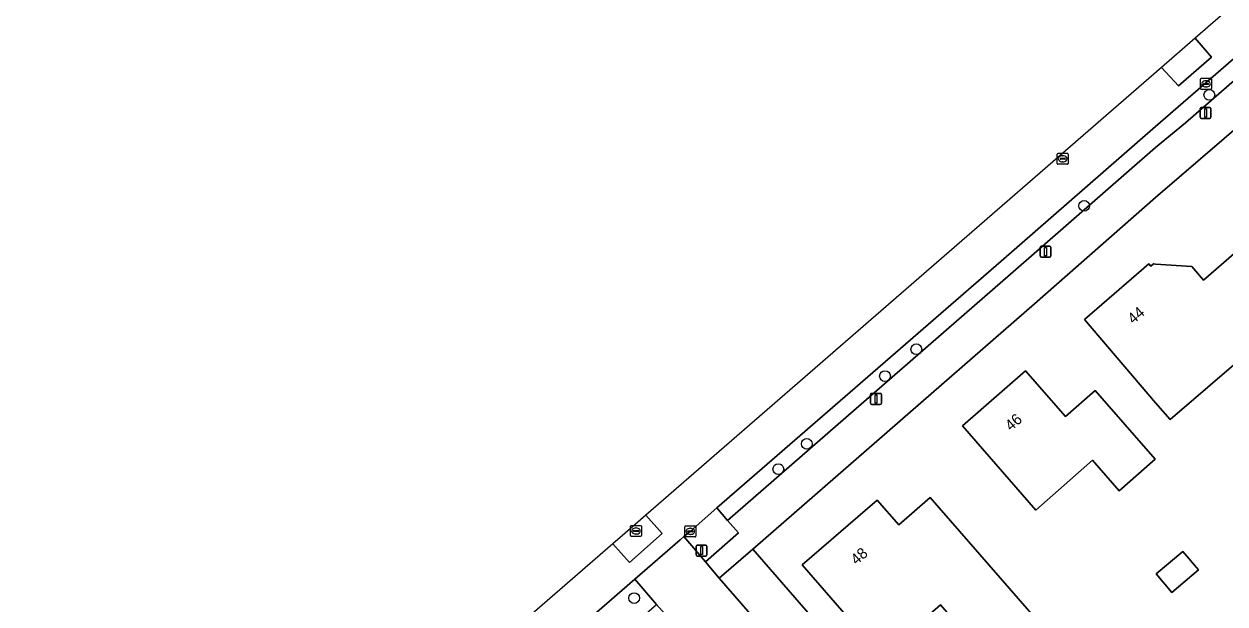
# Model space of a CAD drawing. Extents: x 155887 to 156869, y 383880 to 384678.
# Drawn here: x 155897.1 to 156006.3, y 384066 to 384118.8 of the extents above; entities that cross this region are included whole.
import ezdxf

# ---------------------------------------------------------------- set-up
doc = ezdxf.new("R2010")
doc.units = 0
for name, color, linetype in [('IMGEO_Boom', 7, 'Continuous'), ('IMGEO_Erf', 7, 'Continuous'), ('IMGEO_Groenvoorziening', 7, 'Continuous'), ('IMGEO_Kolk', 7, 'Continuous'), ('IMGEO_Lichtmast', 7, 'Continuous'), ('IMGEO_Pand', 7, 'Continuous'), ('IMGEO_Pand_nummerreeks', 7, 'Continuous'), ('IMGEO_Parkeervlak_open', 7, 'Continuous'), ('IMGEO_Rijbaan_lokaal_gesloten', 7, 'Continuous'), ('IMGEO_Rijbaan_lokaal_open', 7, 'Continuous'), ('IMGEO_Rioolput', 7, 'Continuous'), ('IMGEO_Verkeerseiland_groen', 7, 'Continuous'), ('IMGEO_Voetpad_open', 7, 'Continuous')]:
    doc.layers.add(name, color=color, linetype=linetype)

msp = doc.modelspace()

# ---------------------------------------------------------------- linework, layer by layer
at = {"layer": 'IMGEO_Boom'}
for centre in [(156004.89, 384112.32), (155993.51, 384102.23), (155978.24, 384089.19), (155975.39, 384086.75), (155968.28, 384080.59), (155965.69, 384078.29), (155952.58, 384066.56)]:
    msp.add_circle(centre, 0.489, dxfattribs=at)
at = {"layer": 'IMGEO_Erf'}
msp.add_lwpolyline([(156014.63, 384115.56), (156000, 384102.99), (155988.99, 384093.32), (155963.36, 384071.02), (155979.83, 384052.07), (155979.86, 384052.09), (155982.63, 384048.87), (155983.24, 384048.16), (155986.68, 384044.16), (155986.94, 384044.39), (155990.61, 384047.62), (155989.41, 384048.97), (155993.24, 384052.33), (155997.05, 384055.54), (155998.16, 384054.27), (156000, 384055.89), (156001.81, 384057.42), (156005.54, 384060.57), (156004.36, 384061.93), (156008.14, 384065.22)], dxfattribs=at)
for points in [[(156009.74, 384086.87), (156008.18, 384088.68), (156001.34, 384082.8), (156000, 384084.31), (155993.53, 384091.9), (155999.39, 384096.97), (155999.57, 384096.76), (155999.8, 384096.95), (156000, 384096.94), (156003.29, 384096.71), (156004.36, 384095.46), (156007.36, 384098.07), (156013.9, 384090.47)], [(155999.96, 384079.18), (155996.69, 384076.32), (155994.26, 384079.09), (155989.1, 384074.57), (155982.43, 384082.21), (155988.18, 384087.23), (155991.81, 384083.08), (155994.51, 384085.43)], [(155985.06, 384060.65), (155980.45, 384065.94), (155975.09, 384061.27), (155967.87, 384069.58), (155974.68, 384075.48), (155976.64, 384073.22), (155979.51, 384075.71), (155989.36, 384064.39)], [(156003.9, 384069.12), (156001.48, 384067.08), (156000.05, 384068.77), (156002.47, 384070.81)]]:
    msp.add_lwpolyline(points, close=True, dxfattribs=at)
at = {"layer": 'IMGEO_Groenvoorziening'}
msp.add_lwpolyline([(155979.86, 384052.09), (155979.83, 384052.07), (155963.36, 384071.02), (155960.32, 384068.38), (155979.58, 384046.21), (155982.63, 384048.87)], close=True, dxfattribs=at)
at = {"layer": 'IMGEO_Kolk'}
for p, q in [((156004.09, 384112.9), (156004.09, 384113.75)), ((156004.16, 384113.83), (156005.02, 384113.83)), ((156005.02, 384112.82), (156004.16, 384112.82)), ((156004.35, 384113.32), (156004.35, 384113.33)), ((156004.39, 384113.37), (156004.79, 384113.37)), ((156004.78, 384113.28), (156004.39, 384113.28)), ((156004.6, 384113.05), (156004.57, 384113.05)), ((156004.58, 384113.6), (156004.6, 384113.6)), ((156004.83, 384113.33), (156004.83, 384113.32)), ((156005.09, 384113.75), (156005.09, 384112.9)), ((155957.18, 384072.2), (155957.18, 384073.05)), ((155957.26, 384073.13), (155958.11, 384073.13)), ((155957.44, 384072.62), (155957.44, 384072.64)), ((155957.48, 384072.67), (155957.88, 384072.67)), ((155957.88, 384072.59), (155957.48, 384072.59)), ((155957.67, 384072.91), (155957.69, 384072.91)), ((155957.92, 384072.64), (155957.92, 384072.62)), ((155958.18, 384073.05), (155958.18, 384072.2)), ((155958.11, 384072.13), (155957.26, 384072.13)), ((155957.69, 384072.35), (155957.67, 384072.35))]:
    msp.add_line(p, q, dxfattribs=at)
for points in [[(156004.09, 384112.9), (156004.09, 384113.75)], [(156004.16, 384113.83), (156005.02, 384113.83)], [(156005.02, 384112.82), (156004.16, 384112.82)], [(156005.09, 384113.75), (156005.09, 384112.9)], [(155957.18, 384072.2), (155957.18, 384073.05)], [(155957.26, 384073.13), (155958.11, 384073.13)], [(155958.18, 384073.05), (155958.18, 384072.2)], [(155958.11, 384072.13), (155957.26, 384072.13)]]:
    msp.add_lwpolyline(points, dxfattribs=at)
for centre, radius, start, end in [((156004.16, 384113.75), 0.0765, 91.552, 178.448), ((156004.16, 384113.75), 0.0765, 91.552, 178.448), ((156004.16, 384112.9), 0.0765, 181.552, 268.448), ((156004.16, 384112.9), 0.0765, 181.552, 268.448), ((156004.39, 384113.33), 0.0403, 85.8775, 175.7526), ((156004.38, 384113.32), 0.0366, 178.938, 274.7102), ((156004.79, 384113.32), 0.043, 264.8664, 352.4533), ((156004.79, 384113.33), 0.0386, 1.7309, 96.639), ((156005.01, 384113.75), 0.0765, 1.552, 88.448), ((156005.01, 384113.75), 0.0765, 1.552, 88.448), ((156005.01, 384112.9), 0.0765, 271.552, 358.448), ((156005.01, 384112.9), 0.0765, 271.552, 358.448), ((155957.26, 384073.05), 0.0765, 91.552, 178.448), ((155957.26, 384073.05), 0.0765, 91.552, 178.448), ((155957.48, 384072.63), 0.0403, 85.8775, 175.7526), ((155957.48, 384072.62), 0.0366, 178.938, 274.7102), ((155957.89, 384072.63), 0.0386, 1.7309, 96.639), ((155957.88, 384072.63), 0.043, 264.8664, 352.4533), ((155958.11, 384073.05), 0.0765, 1.552, 88.448), ((155958.11, 384073.05), 0.0765, 1.552, 88.448), ((155957.26, 384072.2), 0.0765, 181.552, 268.448), ((155957.26, 384072.2), 0.0765, 181.552, 268.448), ((155958.11, 384072.2), 0.0765, 271.552, 358.448), ((155958.11, 384072.2), 0.0765, 271.552, 358.448)]:
    msp.add_arc(centre, radius, start, end, dxfattribs=at)
for centre, major_axis, ratio, start_param, end_param in [((156004.58, 384113.32), (-0.387, 0.002), 0.722429, 4.712389, 7.853982), ((156004.6, 384113.32), (-0.39, 0.002), 0.717154, 1.570796, 4.712389), ((155957.67, 384072.63), (-0.387, 0.002), 0.722429, 4.712389, 7.853982), ((155957.69, 384072.63), (-0.39, 0.002), 0.717154, 1.570796, 4.712389)]:
    msp.add_ellipse(centre, major_axis=major_axis, ratio=ratio, start_param=start_param, end_param=end_param, dxfattribs=at)
at = {"layer": 'IMGEO_Lichtmast'}
for p, q in [((156004.05, 384110.28), (156004.05, 384111.08)), ((156004.05, 384111.08), (156004.05, 384110.28)), ((156004.15, 384111.18), (156004.94, 384111.18)), ((156004.94, 384111.18), (156004.15, 384111.18)), ((156005.04, 384111.08), (156005.04, 384110.28)), ((156005.04, 384110.28), (156005.04, 384111.08)), ((156004.94, 384110.18), (156004.15, 384110.18)), ((156004.15, 384110.18), (156004.94, 384110.18)), ((155989.5, 384097.66), (155989.5, 384098.46)), ((155989.5, 384098.46), (155989.5, 384097.66)), ((155989.6, 384098.56), (155990.38, 384098.56)), ((155990.38, 384098.56), (155989.6, 384098.56)), ((155990.38, 384097.56), (155989.6, 384097.56)), ((155989.6, 384097.56), (155990.38, 384097.56)), ((155990.48, 384098.46), (155990.48, 384097.66)), ((155990.48, 384097.66), (155990.48, 384098.46)), ((155974.07, 384084.28), (155974.07, 384085.08)), ((155974.07, 384085.08), (155974.07, 384084.28)), ((155974.17, 384085.18), (155974.96, 384085.18)), ((155974.96, 384085.18), (155974.17, 384085.18)), ((155975.06, 384085.08), (155975.06, 384084.28)), ((155975.06, 384084.28), (155975.06, 384085.08)), ((155974.96, 384084.18), (155974.17, 384084.18)), ((155974.17, 384084.18), (155974.96, 384084.18)), ((155958.31, 384071.38), (155959.1, 384071.38)), ((155959.1, 384071.38), (155958.31, 384071.38)), ((155958.21, 384070.48), (155958.21, 384071.28)), ((155958.21, 384071.28), (155958.21, 384070.48)), ((155959.1, 384070.38), (155958.31, 384070.38)), ((155958.31, 384070.38), (155959.1, 384070.38)), ((155959.2, 384071.28), (155959.2, 384070.48)), ((155959.2, 384070.48), (155959.2, 384071.28))]:
    msp.add_line(p, q, dxfattribs=at)
for points in [[(156004.47, 384111.06), (156004.62, 384111.06), (156004.62, 384110.31), (156004.47, 384110.31), (156004.47, 384111.06)], [(155989.91, 384098.43), (155990.07, 384098.43), (155990.07, 384097.68), (155989.91, 384097.68), (155989.91, 384098.43)], [(155974.49, 384085.05), (155974.64, 384085.05), (155974.64, 384084.3), (155974.49, 384084.3), (155974.49, 384085.05)], [(155958.63, 384071.26), (155958.78, 384071.26), (155958.78, 384070.51), (155958.63, 384070.51), (155958.63, 384071.26)]]:
    msp.add_lwpolyline(points, dxfattribs=at)
for centre, start, end in [((156004.15, 384111.08), 90, 180), ((156004.15, 384111.08), 90, 180), ((156004.94, 384111.08), 0, 90), ((156004.94, 384111.08), 360, 90), ((156004.15, 384110.28), 180, 270), ((156004.15, 384110.28), 180, 270), ((156004.94, 384110.28), 270, 0), ((156004.94, 384110.28), 270, 0), ((155989.6, 384098.46), 90, 180), ((155989.6, 384098.46), 90, 180), ((155989.6, 384097.66), 180, 270), ((155989.6, 384097.66), 180, 270), ((155990.38, 384098.46), 0, 90), ((155990.38, 384098.46), 360, 90), ((155990.38, 384097.66), 270, 0), ((155990.38, 384097.66), 270, 0), ((155974.17, 384085.08), 90, 180), ((155974.17, 384085.08), 90, 180), ((155974.96, 384085.08), 0, 90), ((155974.96, 384085.08), 360, 90), ((155974.17, 384084.28), 180, 270), ((155974.17, 384084.28), 180, 270), ((155974.96, 384084.28), 270, 0), ((155974.96, 384084.28), 270, 0), ((155958.31, 384071.28), 90, 180), ((155958.31, 384071.28), 90, 180), ((155959.1, 384071.28), 0, 90), ((155959.1, 384071.28), 360, 90), ((155958.31, 384070.48), 180, 270), ((155958.31, 384070.48), 180, 270), ((155959.1, 384070.48), 270, 0), ((155959.1, 384070.48), 270, 0)]:
    msp.add_arc(centre, 0.1, start, end, dxfattribs=at)
at = {"layer": 'IMGEO_Pand'}
for points in [[(156001.34, 384082.8), (156008.18, 384088.68), (156009.74, 384086.87), (156013.9, 384090.47), (156007.36, 384098.07), (156004.36, 384095.46), (156003.29, 384096.71), (156000, 384096.94), (155999.8, 384096.95), (155999.57, 384096.76), (155999.39, 384096.97), (155993.53, 384091.9), (156000, 384084.31)], [(155989.1, 384074.57), (155994.26, 384079.09), (155996.69, 384076.32), (155999.96, 384079.18), (155994.51, 384085.43), (155991.81, 384083.08), (155988.18, 384087.23), (155982.43, 384082.21)], [(155985.06, 384060.65), (155989.36, 384064.39), (155979.51, 384075.71), (155976.64, 384073.22), (155974.68, 384075.48), (155967.87, 384069.58), (155975.09, 384061.27), (155980.45, 384065.94)], [(156002.47, 384070.81), (156000.05, 384068.77), (156001.48, 384067.08), (156003.9, 384069.12)]]:
    msp.add_lwpolyline(points, close=True, dxfattribs=at)
at = {"layer": 'IMGEO_Parkeervlak_open'}
for points in [[(155960.1, 384074.77), (155961.08, 384073.63), (155986.8, 384096.01), (156000, 384107.53), (156002.74, 384109.77), (156037.98, 384140.49), (156053.51, 384154.06), (156081.12, 384178.03), (156143.77, 384232.36), (156142.79, 384233.53), (156142.14, 384232.99), (156099.17, 384195.6), (156079.59, 384178.58), (156052.58, 384155.08), (156037.06, 384141.6), (156000, 384109.46), (155985.96, 384097.2)], [(155909.63, 384030.91), (155910.59, 384029.76), (155949, 384063.19), (155950, 384061.97), (155954.62, 384065.98), (155952.63, 384068.29), (155910.18, 384031.41)]]:
    msp.add_lwpolyline(points, close=True, dxfattribs=at)
at = {"layer": 'IMGEO_Rijbaan_lokaal_gesloten'}
for points in [[(155907.43, 384029.67), (155909.32, 384031.28), (155909.63, 384030.91), (155910.18, 384031.41), (155952.63, 384068.29), (155956.76, 384071.86), (155957.11, 384072.16), (155957.68, 384072.63), (155960.1, 384074.77), (155985.96, 384097.2), (156000, 384109.46), (156037.06, 384141.6), (156052.58, 384155.08), (156079.59, 384178.58), (156099.17, 384195.6), (156142.14, 384232.99)], [(156047.55, 384155.61), (156003.6, 384117.47), (156003.6, 384117.47), (156005.1, 384115.76), (156002.08, 384113.13), (156000.55, 384114.82), (156000.55, 384114.82), (155953.65, 384074.11), (155953.65, 384074.11), (155955.12, 384072.42), (155952.15, 384069.79), (155950.63, 384071.49), (155950.63, 384071.49), (155904.53, 384031.47), (155897.08, 384011.8)]]:
    msp.add_lwpolyline(points, dxfattribs=at)
at = {"layer": 'IMGEO_Rijbaan_lokaal_open'}
for points in [[(156000.55, 384114.82), (156000.55, 384114.82), (156002.08, 384113.13), (156005.1, 384115.76), (156003.6, 384117.47), (156003.6, 384117.47)], [(155950.63, 384071.49), (155950.63, 384071.49), (155952.15, 384069.79), (155955.12, 384072.42), (155953.65, 384074.11), (155953.65, 384074.11), (155952.44, 384073.05)]]:
    msp.add_lwpolyline(points, close=True, dxfattribs=at)
for points in [[(155960.32, 384068.38), (155959.07, 384069.87), (155957.11, 384072.16), (155956.76, 384071.86), (155952.63, 384068.29), (155954.62, 384065.98), (155955.95, 384064.48), (155988.81, 384026.65), (155989.25, 384026.11), (155991.72, 384023.33), (155991.36, 384023.03)], [(155995.84, 384027.51), (155994.25, 384029.36), (155993.27, 384030.54), (155989.3, 384035.02), (155980.19, 384045.51), (155979.58, 384046.21), (155960.32, 384068.38)]]:
    msp.add_lwpolyline(points, dxfattribs=at)
at = {"layer": 'IMGEO_Rioolput'}
for p, q in [((155991.06, 384106.09), (155991.06, 384106.94)), ((155991.13, 384107.01), (155991.98, 384107.01)), ((155991.32, 384106.51), (155991.32, 384106.52)), ((155991.36, 384106.56), (155991.76, 384106.56)), ((155991.75, 384106.47), (155991.36, 384106.47)), ((155991.55, 384106.79), (155991.57, 384106.79)), ((155991.8, 384106.52), (155991.8, 384106.51)), ((155992.06, 384106.94), (155992.06, 384106.09)), ((155991.98, 384106.01), (155991.13, 384106.01)), ((155991.57, 384106.23), (155991.54, 384106.23)), ((155952.24, 384072.24), (155952.24, 384073.09)), ((155952.32, 384073.17), (155953.17, 384073.17)), ((155952.5, 384072.66), (155952.5, 384072.67)), ((155952.54, 384072.71), (155952.94, 384072.71)), ((155952.94, 384072.62), (155952.54, 384072.62)), ((155952.73, 384072.94), (155952.75, 384072.94)), ((155952.98, 384072.67), (155952.98, 384072.66)), ((155953.24, 384073.09), (155953.24, 384072.24)), ((155953.17, 384072.16), (155952.32, 384072.16)), ((155952.75, 384072.39), (155952.73, 384072.39))]:
    msp.add_line(p, q, dxfattribs=at)
for points in [[(155991.06, 384106.09), (155991.06, 384106.94)], [(155991.13, 384107.01), (155991.98, 384107.01)], [(155992.06, 384106.94), (155992.06, 384106.09)], [(155991.98, 384106.01), (155991.13, 384106.01)], [(155952.24, 384072.24), (155952.24, 384073.09)], [(155952.32, 384073.17), (155953.17, 384073.17)], [(155953.24, 384073.09), (155953.24, 384072.24)], [(155953.17, 384072.16), (155952.32, 384072.16)]]:
    msp.add_lwpolyline(points, dxfattribs=at)
for centre, radius, start, end in [((155991.13, 384106.94), 0.0765, 91.552, 178.448), ((155991.13, 384106.94), 0.0765, 91.552, 178.448), ((155991.36, 384106.52), 0.0403, 85.8775, 175.7526), ((155991.35, 384106.51), 0.0366, 178.938, 274.7102), ((155991.76, 384106.51), 0.043, 264.8664, 352.4533), ((155991.76, 384106.52), 0.0386, 1.7309, 96.639), ((155991.98, 384106.94), 0.0765, 1.552, 88.448), ((155991.98, 384106.94), 0.0765, 1.552, 88.448), ((155991.13, 384106.09), 0.0765, 181.552, 268.448), ((155991.13, 384106.09), 0.0765, 181.552, 268.448), ((155991.98, 384106.09), 0.0765, 271.552, 358.448), ((155991.98, 384106.09), 0.0765, 271.552, 358.448), ((155952.32, 384073.09), 0.0765, 91.552, 178.448), ((155952.32, 384073.09), 0.0765, 91.552, 178.448), ((155952.54, 384072.67), 0.0403, 85.8775, 175.7526), ((155952.54, 384072.66), 0.0366, 178.938, 274.7102), ((155952.95, 384072.67), 0.0386, 1.7309, 96.639), ((155952.94, 384072.66), 0.043, 264.8664, 352.4533), ((155953.17, 384073.09), 0.0765, 1.552, 88.448), ((155953.17, 384073.09), 0.0765, 1.552, 88.448), ((155952.32, 384072.24), 0.0765, 181.552, 268.448), ((155952.32, 384072.24), 0.0765, 181.552, 268.448), ((155953.17, 384072.24), 0.0765, 271.552, 358.448), ((155953.17, 384072.24), 0.0765, 271.552, 358.448)]:
    msp.add_arc(centre, radius, start, end, dxfattribs=at)
for centre, major_axis, ratio, start_param, end_param in [((155991.54, 384106.51), (-0.387, 0.002), 0.722429, 4.712389, 7.853982), ((155991.57, 384106.51), (-0.39, 0.002), 0.717154, 1.570796, 4.712389), ((155952.73, 384072.66), (-0.387, 0.002), 0.722429, 4.712389, 7.853982), ((155952.75, 384072.66), (-0.39, 0.002), 0.717154, 1.570796, 4.712389)]:
    msp.add_ellipse(centre, major_axis=major_axis, ratio=ratio, start_param=start_param, end_param=end_param, dxfattribs=at)
at = {"layer": 'IMGEO_Verkeerseiland_groen'}
msp.add_lwpolyline([(155962.06, 384072.5), (155961.08, 384073.63), (155960.1, 384074.77), (155957.68, 384072.63), (155957.11, 384072.16), (155959.07, 384069.87)], close=True, dxfattribs=at)
at = {"layer": 'IMGEO_Voetpad_open'}
msp.add_lwpolyline([(156142.79, 384233.53), (156143.77, 384232.36), (156081.12, 384178.03), (156053.51, 384154.06), (156037.98, 384140.49), (156002.74, 384109.77), (156000, 384107.53), (155986.8, 384096.01), (155961.08, 384073.63), (155962.06, 384072.5), (155959.07, 384069.87), (155960.32, 384068.38), (155963.36, 384071.02), (155988.99, 384093.32), (156000, 384102.99), (156014.63, 384115.56), (156040.2, 384137.76), (156053.51, 384149.41), (156055.79, 384151.36), (156083.27, 384175.3)], dxfattribs=at)

# ---------------------------------------------------------------- texts
at = {"layer": 'IMGEO_Pand_nummerreeks'}
for s, rotation, p in [('44', 40.8812, (155997.98, 384091.42)), ('46', 41.1274, (155986.84, 384081.7)), ('48', 40.9484, (155972.8, 384069.52))]:
    msp.add_text(s, height=1, rotation=rotation, dxfattribs=at).set_placement(p)

doc.saveas('drawing.dxf')
